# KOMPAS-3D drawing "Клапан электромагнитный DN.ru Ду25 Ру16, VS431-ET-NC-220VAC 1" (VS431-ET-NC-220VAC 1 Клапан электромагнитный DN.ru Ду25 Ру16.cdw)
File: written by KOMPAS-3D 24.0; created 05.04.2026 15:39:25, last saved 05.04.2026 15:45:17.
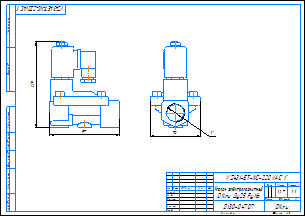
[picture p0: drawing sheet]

Document properties: c3d_UniqueCompID: ef56311e-7521-43dc-8291-0e6108b3d81d; Автор: artio; Класс точности: c; Знак неуказанной шероховатости: Шероховатость не задана; Рассекать на разрезах: Да; c3d_UniqueCompID: ef56311e-7521-43dc-8291-0e6108b3d81d; Автор: artio; Класс точности: c; Знак неуказанной шероховатости: Шероховатость не задана; Рассекать на разрезах: Да; Автор: artio; Форматы листов документа: A3; Полное имя файла: VS431-ET-NC-220VAC 1 Клапан электромагнитный DN.ru Ду25 Ру16.m3d; Масса: 1.267; Наименование: Клапан электромагнитный DN.ru Ду25 Ру16; Количество листов документа: 1; Примечание: D130-04707

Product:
- Body: Тело 1  | qty 1
    Масса: 1.729172
- Part/product: Клапан электромагнитный DN.ru Ду25 Ру16  | designation VS431-ET-NC-220VAC 1
    Масса: 1.267
    Раздел спецификации: Прочие изделия
    Примечание: D130-04707
    additional columns: ef56311e-7521-43dc-8291-0e6108b3d81d; artio; c; Шероховатость не задана; Да

Views: Вид 1, Спереди, Проекционный вид 2
Referenced files in C:\Users\artio\OneDrive\Рабочий стол\Клапан электромагнитный DN.ru\VS431\VS431-ET-NC\: VS431-ET-NC-220VAC 3-4 Клапан электромагнитный DN.ru Ду20 Ру16.m3d, VS431-ET-NC-220VAC 1 Клапан электромагнитный DN.ru Ду25 Ру16.m3d, VS431-ET-NC-220VAC 3-4 Клапан электромагнитный DN.ru Ду20 Ру16.cdw
Referenced files in C:\Users\artio\OneDrive\Рабочий стол\Клапан электромагнитный DN.ru\VS431\VS431-ET-NC\VS431-ET-NC-220VAC\Ду25\: VS431-ET-NC-220VAC 1 Клапан электромагнитный DN.ru Ду25 Ру16.m3d
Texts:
  VS431-ET-NC-220VAC 1
  Клапан электромагнитный
  DN.ru Ду25 Ру16
  VS431-ET-NC-220VAC 1"
  VS431-ET-NC-220VAC 1"-
  Клапан электромагнитный DN.ru Ду25 Ру16
  VS431-ET-NC-220VAC 1 Клапан электромагнитный DN.ru Ду25 Ру16
Dimensions and other numbers on the sheet: 0; 3; 2; 4; 70; 97; 119; 1:1; 1; 1,27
